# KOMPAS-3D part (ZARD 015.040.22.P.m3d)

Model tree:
1. Плоскость XY
2. Плоскость ZX
3. Плоскость ZY
4. Ось X
5. Ось Y
6. Ось Z
7. Начало координат
8. Смещенная плоскость:2
     Расстояние = 77.5
9. Булева операция:1
10. Булева операция:3
11. Булева операция:5
12. Булева операция:6
